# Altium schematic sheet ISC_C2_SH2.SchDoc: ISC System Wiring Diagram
size C; DrawnBy: Filiberto Clara; Engineer: Filiberto Clara; Organization: LIGO Laboratory; Address1: California Institute of Technology; Address2: Massachusetts Institute of Technology; SheetNumber: 4; SheetTotal: 39
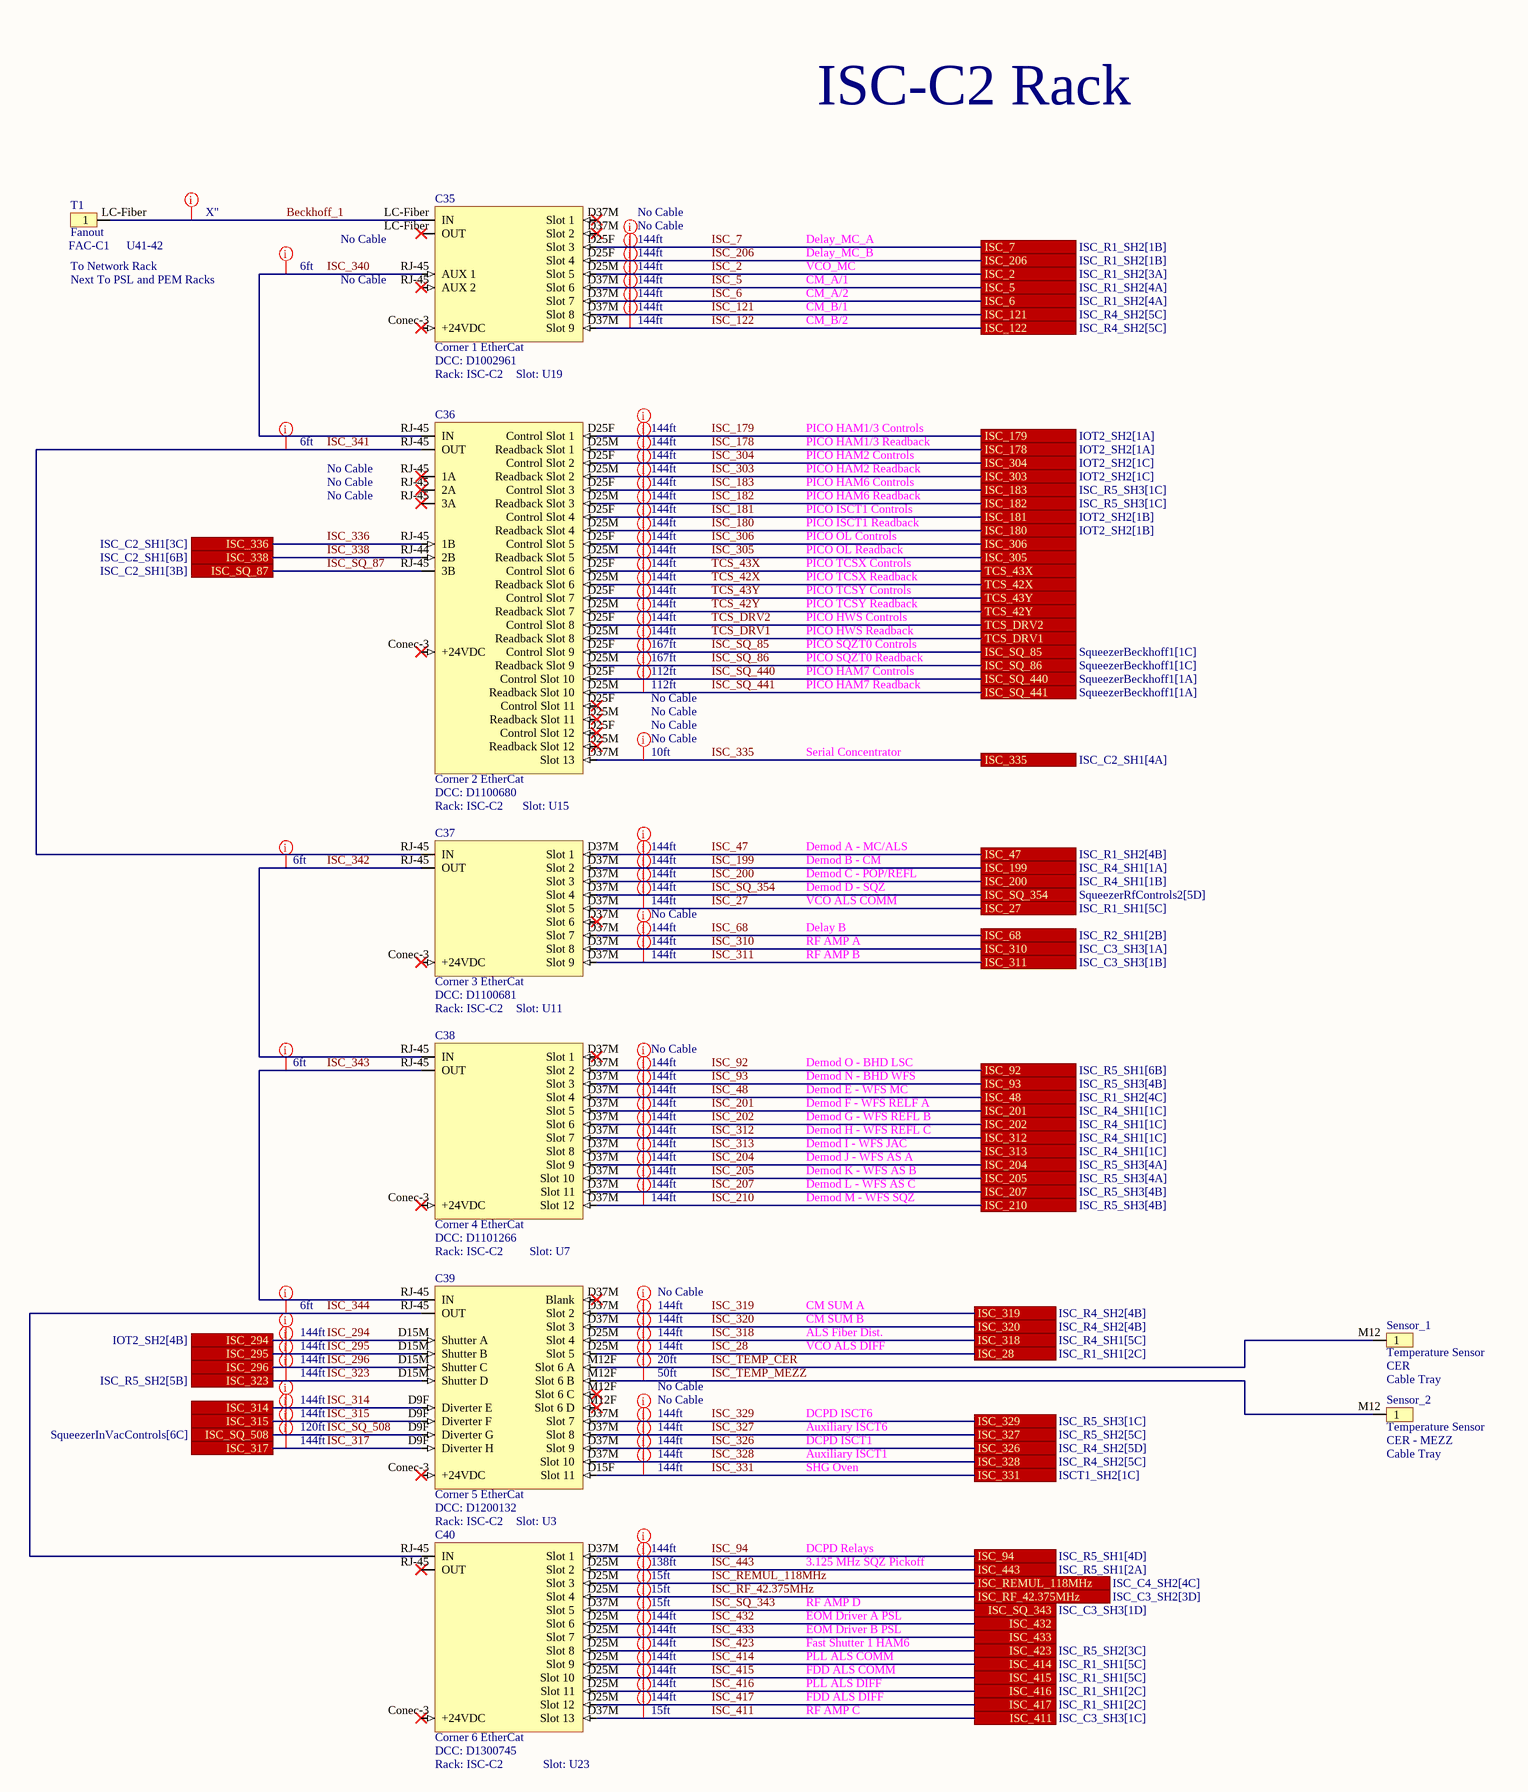
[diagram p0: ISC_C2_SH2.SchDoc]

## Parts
C35  Corner 1 EtherCat  DCC: D1002961  Rack: ISC-C2  Slot: U19
C36  Corner 2 EtherCat  DCC: D1100680  Rack: ISC-C2  Slot: U15
C37  Corner 3 EtherCat  DCC: D1100681  Rack: ISC-C2  Slot: U11
C38  Corner 4 EtherCat  DCC: D1101266  Rack: ISC-C2  Slot: U7
C39  Corner 5 EtherCat  DCC: D1200132  Rack: ISC-C2  Slot: U3
C40  Corner 6 EtherCat  DCC: D1300745  Rack: ISC-C2  Slot: U23
Sensor_1  Temperature Sensor  Rack: CER  Slot: Cable Tray
Sensor_2  Temperature Sensor  Rack: CER - MEZZ  Slot: Cable Tray
T1  Fanout  Rack: FAC-C1  Slot: U41-42

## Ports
ISC_2 (see ISC_R1_SH2[3A]), ISC_5 (see ISC_R1_SH2[4A]), ISC_6 (see ISC_R1_SH2[4A]), ISC_7 (see ISC_R1_SH2[1B]), ISC_27 (see ISC_R1_SH1[5C]), ISC_28 (see ISC_R1_SH1[2C]), ISC_47 (see ISC_R1_SH2[4B]), ISC_48 (see ISC_R1_SH2[4C]), ISC_68 (see ISC_R2_SH1[2B]), ISC_92 (see ISC_R5_SH1[6B]), ISC_93 (see ISC_R5_SH3[4B]), ISC_94 (see ISC_R5_SH1[4D]), ISC_121 (see ISC_R4_SH2[5C]), ISC_122 (see ISC_R4_SH2[5C]), ISC_178 (see IOT2_SH2[1A]), ISC_179 (see IOT2_SH2[1A]), ISC_180 (see IOT2_SH2[1B]), ISC_181 (see IOT2_SH2[1B]), ISC_182 (see ISC_R5_SH3[1C]), ISC_183 (see ISC_R5_SH3[1C]), ISC_199 (see ISC_R4_SH1[1A]), ISC_200 (see ISC_R4_SH1[1B]), ISC_201 (see ISC_R4_SH1[1C]), ISC_202 (see ISC_R4_SH1[1C]), ISC_204 (see ISC_R5_SH3[4A]), ISC_205 (see ISC_R5_SH3[4A]), ISC_206 (see ISC_R1_SH2[1B]), ISC_207 (see ISC_R5_SH3[4B]), ISC_210 (see ISC_R5_SH3[4B]), ISC_294 (see IOT2_SH2[4B]), ISC_295, ISC_296, ISC_303 (see IOT2_SH2[1C]), ISC_304 (see IOT2_SH2[1C]), ISC_305, ISC_306, ISC_310 (see ISC_C3_SH3[1A]), ISC_311 (see ISC_C3_SH3[1B]), ISC_312 (see ISC_R4_SH1[1C]), ISC_313 (see ISC_R4_SH1[1C]), ISC_314, ISC_315, ISC_317, ISC_318 (see ISC_R4_SH1[5C]), ISC_319 (see ISC_R4_SH2[4B]), ISC_320 (see ISC_R4_SH2[4B]), ISC_323 (see ISC_R5_SH2[5B]), ISC_326 (see ISC_R4_SH2[5D]), ISC_327 (see ISC_R5_SH2[5C]), ISC_328 (see ISC_R4_SH2[5C]), ISC_329 (see ISC_R5_SH3[1C]), ISC_331 (see ISCT1_SH2[1C]), ISC_335 (see ISC_C2_SH1[4A]), ISC_336 (see ISC_C2_SH1[3C]), ISC_338 (see ISC_C2_SH1[6B]), ISC_411 (see ISC_C3_SH3[1C]), ISC_414 (see ISC_R1_SH1[5C]), ISC_415 (see ISC_R1_SH1[5C]), ISC_416 (see ISC_R1_SH1[2C]), ISC_417 (see ISC_R1_SH1[2C]), ISC_423 (see ISC_R5_SH2[3C]), ISC_432, ISC_433, ISC_443 (see ISC_R5_SH1[2A]), ISC_REMUL_118MHz (see ISC_C4_SH2[4C]), ISC_RF_42.375MHz (see ISC_C3_SH2[3D]), ISC_SQ_85 (see SqueezerBeckhoff1[1C]), ISC_SQ_86 (see SqueezerBeckhoff1[1C]), ISC_SQ_87 (see ISC_C2_SH1[3B]), ISC_SQ_343 (see ISC_C3_SH3[1D]), ISC_SQ_354 (see SqueezerRfControls2[5D]), ISC_SQ_440 (see SqueezerBeckhoff1[1A]), ISC_SQ_441 (see SqueezerBeckhoff1[1A]), ISC_SQ_508 (see SqueezerInVacControls[6C]), TCS_42X, TCS_42Y, TCS_43X, TCS_43Y, TCS_DRV1, TCS_DRV2

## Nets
Beckhoff_1: C35.LC-Fiber(IN) T1.LC-Fiber(1)
ISC_2: C35.D25M(Slot_5) ; port ISC_2
ISC_5: C35.D37M(Slot_1) ; port ISC_5
ISC_6: C35.D37M(Slot_7) ; port ISC_6
ISC_7: C35.D25F(Slot_3) ; port ISC_7
ISC_27: C37.D37M(Slot_5) ; port ISC_27
ISC_28: C39.D25M(Slot_5) ; port ISC_28
ISC_47: C37.D37M(Slot_1) ; port ISC_47
ISC_48: C38.D37M(Slot_4) ; port ISC_48
ISC_68: C37.D37M(Slot_7) ; port ISC_68
ISC_92: C38.D37M(Slot_1) ; port ISC_92
ISC_93: C38.D37M(Slot_3) ; port ISC_93
ISC_94: C40.D37M(Slot_1) ; port ISC_94
ISC_121: C35.D37M(Slot_8) ; port ISC_121
ISC_122: C35.D37M(Slot_9) ; port ISC_122
ISC_178: C36.D25M(Readback_Slot_1) ; port ISC_178
ISC_179: C36.D25F(Control_Slot_1) ; port ISC_179
ISC_180: C36.D25M(Readback_Slot_4) ; port ISC_180
ISC_181: C36.D25F(Control_Slot_4) ; port ISC_181
ISC_182: C36.D25M(Readback_Slot_3) ; port ISC_182
ISC_183: C36.D25F(Control_Slot_3) ; port ISC_183
ISC_199: C37.D37M(Slot_2) ; port ISC_199
ISC_200: C37.D37M(Slot_3) ; port ISC_200
ISC_201: C38.D37M(Slot_5) ; port ISC_201
ISC_202: C38.D37M(Slot_6) ; port ISC_202
ISC_204: C38.D37M(Slot_9) ; port ISC_204
ISC_205: C38.D37M(Slot_10) ; port ISC_205
ISC_206: C35.D25F(Slot_4) ; port ISC_206
ISC_207: C38.D37M(Slot_11) ; port ISC_207
ISC_210: C38.D37M(Slot_12) ; port ISC_210
ISC_294: C39.D15M(Shutter_A) ; port ISC_294
ISC_295: C39.D15M(Shutter_B) ; port ISC_295
ISC_296: C39.D15M(Shutter_C) ; port ISC_296
ISC_303: C36.D25M(Readback_Slot_2) ; port ISC_303
ISC_304: C36.D25F(Control_Slot_2) ; port ISC_304
ISC_305: C36.D25M(Readback_Slot_5) ; port ISC_305
ISC_306: C36.D25F(Control_Slot_5) ; port ISC_306
ISC_310: C37.D37M(Slot_8) ; port ISC_310
ISC_311: C37.D37M(Slot_9) ; port ISC_311
ISC_312: C38.D37M(Slot_7) ; port ISC_312
ISC_313: C38.D37M(Slot_8) ; port ISC_313
ISC_314: C39.D9F(Diverter_E) ; port ISC_314
ISC_315: C39.D9F(Diverter_F) ; port ISC_315
ISC_317: C39.D9F(Diverter_H) ; port ISC_317
ISC_318: C39.D25M(Slot_4) ; port ISC_318
ISC_319: C39.D37M(Blank) ; port ISC_319
ISC_320: C39.D37M(Slot_3) ; port ISC_320
ISC_323: C39.D15M(Shutter_D) ; port ISC_323
ISC_326: C39.D37M(Slot_9) ; port ISC_326
ISC_327: C39.D37M(Slot_8) ; port ISC_327
ISC_328: C39.D37M(Slot_10) ; port ISC_328
ISC_329: C39.D37M(Slot_7) ; port ISC_329
ISC_331: C39.D15F(Slot_11) ; port ISC_331
ISC_335: C36.D37M(Slot_13) ; port ISC_335
ISC_336: C36.RJ-45(1B) ; port ISC_336
ISC_338: C36.RJ-44(2B) ; port ISC_338
ISC_340: C35.RJ-45(AUX_1) C36.RJ-45(IN)
ISC_341: C36.RJ-45(OUT) C37.RJ-45(IN)
ISC_342: C37.RJ-45(OUT) C38.RJ-45(IN)
ISC_343: C38.RJ-45(OUT) C39.RJ-45(IN)
ISC_344: C39.RJ-45(OUT) C40.RJ-45(IN)
ISC_411: C40.D37M(Slot_13) ; port ISC_411
ISC_414: C40.D25M(Slot_9) ; port ISC_414
ISC_415: C40.D25M(Slot_10) ; port ISC_415
ISC_416: C40.D25M(Slot_11) ; port ISC_416
ISC_417: C40.D25M(Slot_12) ; port ISC_417
ISC_423: C40.D25M(Slot_8) ; port ISC_423
ISC_432: C40.D25M(Slot_6) ; port ISC_432
ISC_433: C40.D25M(Slot_7) ; port ISC_433
ISC_443: C40.D25M(Slot_2) ; port ISC_443
ISC_REMUL_118MHz: C40.D25M(Slot_3) ; port ISC_REMUL_118MHz
ISC_RF_42.375MHz: C40.D25M(Slot_4) ; port ISC_RF_42.375MHz
ISC_SQ_85: C36.D25F(Control_Slot_9) ; port ISC_SQ_85
ISC_SQ_86: C36.D25M(Readback_Slot_9) ; port ISC_SQ_86
ISC_SQ_87: C36.RJ-45(3B) ; port ISC_SQ_87
ISC_SQ_343: C40.D37M(Slot_5) ; port ISC_SQ_343
ISC_SQ_354: C37.D37M(Slot_4) ; port ISC_SQ_354
ISC_SQ_440: C36.D25F(Control_Slot_10) ; port ISC_SQ_440
ISC_SQ_441: C36.D25M(Readback_Slot_10) ; port ISC_SQ_441
ISC_SQ_508: C39.D9F(Diverter_G) ; port ISC_SQ_508
ISC_TEMP_CER: C39.M12F(Slot_6_A) Sensor_1.M12(1)
ISC_TEMP_MEZZ: C39.M12F(Slot_6_B) Sensor_2.M12(1)
TCS_42X: C36.D25M(Readback_Slot_6) ; port TCS_42X
TCS_42Y: C36.D25M(Readback_Slot_7) ; port TCS_42Y
TCS_43X: C36.D25F(Control_Slot_6) ; port TCS_43X
TCS_43Y: C36.D25F(Control_Slot_7) ; port TCS_43Y
TCS_DRV1: C36.D25M(Readback_Slot_8) ; port TCS_DRV1
TCS_DRV2: C36.D25F(Control_Slot_8) ; port TCS_DRV2

Not connected (* = marked no-connect by the designer): C35 Conec-3(+24VDC)*; C36 Conec-3(+24VDC)*; C37 Conec-3(+24VDC)*; C38 Conec-3(+24VDC)*; C39 Conec-3(+24VDC)*; C40 Conec-3(+24VDC)*

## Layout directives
Length: 144ft: ISC_2, ISC_5, ISC_6, ISC_7, ISC_27, ISC_28, ISC_47, ISC_48, ISC_68, ISC_92, ISC_93, ISC_94, ISC_121, ISC_122, ISC_178, ISC_179, ISC_180, ISC_181, ISC_182, ISC_183, ISC_199, ISC_200, ISC_201, ISC_202, ISC_204, ISC_205, ISC_206, ISC_207, ISC_210, ISC_294, ISC_295, ISC_296, ISC_303, ISC_304, ISC_305, ISC_306, ISC_310, ISC_311, ISC_312, ISC_313, ISC_314, ISC_315, ISC_317, ISC_318, ISC_319, ISC_320, ISC_323, ISC_326, ISC_327, ISC_328, ISC_329, ISC_331, ISC_414, ISC_415, ISC_416, ISC_417, ISC_423, ISC_432, ISC_433, ISC_SQ_354, TCS_42X, TCS_42Y, TCS_43X, TCS_43Y, TCS_DRV1, TCS_DRV2
Length: 6ft: ISC_340, ISC_341, ISC_342, ISC_343, ISC_344
Length: 167ft: ISC_SQ_85, ISC_SQ_86
Length: 15ft: ISC_411, ISC_REMUL_118MHz, ISC_RF_42.375MHz, ISC_SQ_343
Length: 20ft: ISC_TEMP_CER
Length: 50ft: ISC_TEMP_MEZZ
Length: 120ft: ISC_SQ_508
Length: X": Beckhoff_1
Length: 112ft: ISC_SQ_440, ISC_SQ_441
Length: 138ft: ISC_443
Length: 10ft: ISC_335

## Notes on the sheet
- ISC-C2 Rack
- No Cable
- (near T1) To Network Rack
- Next To PSL and PEM Racks
- (near C35) No Cable
- Delay_MC_A
- Delay_MC_B
- VCO_MC
- CM_A/1
- CM_A/2
- CM_B/1
- CM_B/2
- PICO HAM1/3 Controls
- PICO HAM1/3 Readback
- PICO HAM2 Controls
- PICO HAM2 Readback
- PICO HAM6 Controls
- PICO HAM6 Readback
- PICO ISCT1 Controls
- PICO ISCT1 Readback
- PICO OL Controls
- PICO OL Readback
- PICO TCSX Controls
- PICO TCSX Readback
- PICO TCSY Controls
- PICO TCSY Readback
- PICO HWS Controls
- PICO HWS Readback
- PICO SQZT0 Controls
- PICO SQZT0 Readback
- PICO HAM7 Controls
- PICO HAM7 Readback
- Serial Concentrator
- Demod A - MC/ALS
- Demod B - CM
- Demod C - POP/REFL
- Demod D - SQZ
- VCO ALS COMM
- Delay B
- RF AMP A
- RF AMP B
- Demod E - WFS MC
- Demod F - WFS RELF A
- Demod N - BHD WFS
- Demod O - BHD LSC
- Demod G - WFS REFL B
- Demod H - WFS REFL C
- Demod J - WFS AS A
- Demod K - WFS AS B
- Demod I - WFS JAC
- Demod L - WFS AS C
- Demod M - WFS SQZ
- CM SUM A
- CM SUM B
- ALS Fiber Dist.
- VCO ALS DIFF
- DCPD ISCT6
- Auxiliary ISCT6
- DCPD ISCT1
- Auxiliary ISCT1
- SHG Oven
- 3.125 MHz SQZ Pickoff
- DCPD Relays
- RF AMP D
- EOM Driver A PSL
- EOM Driver B PSL
- Fast Shutter 1 HAM6
- RF AMP C
- PLL ALS COMM
- FDD ALS COMM
- PLL ALS DIFF
- FDD ALS DIFF

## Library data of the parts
C35 = Corner 1 EtherCat: Serial: Sxxxxxxx; System: ISC
C36 = Corner 2 EtherCat: Serial: Sxxxxxxx; System: ISC
C37 = Corner 3 EtherCat: Serial: Sxxxxxxx; System: ISC
C38 = Corner 4 EtherCat: Serial: Sxxxxxxx; System: ISC
C39 = Corner 5 EtherCat: Serial: Sxxxxxxx; System: ISC
C40 = Corner 6 EtherCat: Serial: Sxxxxxxx; System: ISC
Sensor_1 Sensor_2 = Placeholder: Placeholder Location; Serial: Sxxxxxxx; System: ISC; DCC: tbd
T1 = Placeholder: Serial: Sxxxxxxx; System: ISC; DCC: tbd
